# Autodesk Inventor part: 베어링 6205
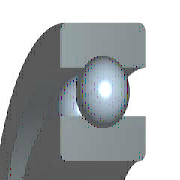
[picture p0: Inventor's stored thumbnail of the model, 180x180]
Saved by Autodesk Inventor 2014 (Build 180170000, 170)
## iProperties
Created: 2015-10
Part Number: 베어링 6205
Material: 강, 연강
Description: 깊은 그루브 볼 베어링
Document SubType Name: Modeling
Standard: KS B 2023
Designer: mdu
Standards Organization: KS
Language: ko-KR
Size Designation: 6205 - 25 x 52 x 15
Categories: <MemberInstance><Categories><Category DisplayName="샤프트 부품" InternalName="7f7aeb1f-a693-4053-b835-cee3144e0d98" Mnemonic="SHFT"><Category DisplayName="베어링" Inter
Density: 7.86 g/cm^3
Appearance: 노란색
Mass: 116.729 g
Surface Area: 107.326 cm^2
Volume: 14.851 cm^3
IsCustomPart: 1
Author: mdu
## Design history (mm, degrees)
sketch "스케치" dims "d0" = 7.02 (= -0.26 x WD + 0.26 x BD)
  geometry: L1 (3.99, 19.25)-(11.01, 19.25); L2 (7.5, 19.25)-(7.5, 15.74); L3 (7.5, 19.25)-(7.5, 22.76); L4 (4.892, 16.901)-(0, 16.901); L5 (0, 12.5)-(15, 12.5); L6 (4.892, 21.599)-(0, 21.599); L7 (0, 26)-(15, 26); L8 (15, 12.5)-(15, 16.901); L9 (10.108, 16.901)-(15, 16.901); L10 (10.108, 21.599)-(15, 21.599); L11 (15, 26)-(15, 21.599); L12 (-1.4, 0)-(8.4, 0) reference; L13 (0, -0.3)-(0, 5.3) reference
  constraints: 22 end point, 4 point on line, 2 collinear, 2 perpendicular, 2 symmetric about line, 1 midpoint, 1 parallel, 14 other
  dimensions: "d9" = 25 diameter of L5 L12 (= WD); "d11" = 52 diameter of L7 L12 (= BD); "d12" = 15 distance between parallel lines of L8 L13 (= KB); "d13" = 33.802 diameter of L9 L12 (= 0.326 x BD + 0.674 x WD)
revolve "본체" stored, may be unused: angle "d6" = 90 deg
revolve "볼" stored, may be unused: angle "d7" = 90 deg
pattern_circular "IDS_ARRAYBALL[SIMPL:T]" dims angle "d3" = 360 deg
body "Solid1"
fillet "모깎기1" dims "d1" = 1 (= KRS)
other parameters: "WD" = 25 [user parameter; used in 5 equation terms], "BD" = 52 [user parameter; used in 5 equation terms], "KB" = 15 [user parameter; used in 1 equation term], "KRS" = 1 [user parameter; used in 1 equation term], "d4" = 0, "d5" = 0, "d8" = 0, "d14" = 0, "d15" = 0, "BBA" = 0 [user parameter], "BC0" = 7800000 [user parameter], "BC" = 1.4e+07 [user parameter], "BR" = 26 (= 0.5 x BD) [user parameter], "WR" = 12.5 (= 0.5 x WD) [user parameter]
